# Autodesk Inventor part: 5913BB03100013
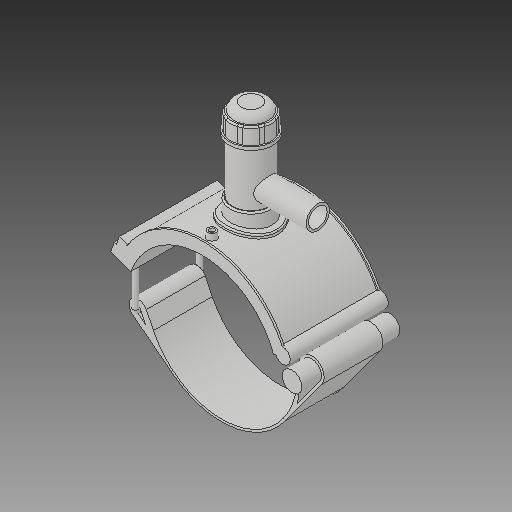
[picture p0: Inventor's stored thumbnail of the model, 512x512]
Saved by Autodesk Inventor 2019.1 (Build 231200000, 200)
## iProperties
Created: 2017-07
Part Number: 5913BB03100013
Material: Generic
Description: PLASSON HIGH VOLUME TAPPING TEE 10''IPS x 1 1/4''IPS
Document SubType Name: Modeling
Designer: KIM
Mass: 1712.7 g
Surface Area: 2671.49 cm^2
Volume: 1712.7 cm^3
Density: 1 g/cm^3
Appearance: Default
Author: KIM
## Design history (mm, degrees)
derived "5913B.ipt"
feature "Solid1::5913B.ipt"
feature "Solid2::5913B.ipt"
feature "Solid4::5913B.ipt"
feature "Solid5::5913B.ipt"
tag "TaggingFeature1"
body "Solid1"
body "Solid2"
other parameters: "d0" = 272.7, "d2" = 449.58, "d3" = 68.175, "d4" = 176.022, "d5" = 0, "d6" = 0.1, "d8" = 0, "d40" = 161.65656, "d41" = 95.445, "d43" = 0, "d45" = 0, "d47" = 261.0522, "d78" = 166.35, "d79" = 15, "d80" = 70.4088, "d82" = 5 deg, "d84" = 4, "d85" = 14, "d86" = 0, "d87" = 3, "d88" = 0, "d96" = 317.09556, "d97" = 3.52044, "d98" = 0, "d102" = 2.727, "d120" = 140 deg, "d121" = 24.228, "d122" = 20 deg, "d123" = 777.195, "d124" = 186.5268, "d126" = 0, "d153" = 176.022, "d154" = 0, "d159" = 7.6356, "d162" = 105.6132, "d163" = 0, "d164" = 136.35, "d169" = 4.0905, "d170" = 11.4534, "d172" = 0, "d173" = 1, "d175" = 136.35, "d176" = 20 deg, "d177" = 19.089, "d178" = 38.178, "d180" = 0, "d183" = 15.2712, "d184" = 15.2712, "d187" = 155.439, "d188" = 11.4534, "d189" = 19.089, "d190" = 0, "d191" = 233.1585, "d193" = 9.8172, "d194" = 4.9086, "d195" = 90 deg, "d197" = 0, "d199" = 0, "d200" = 19.089, "d202" = 0, "d203" = 194.818, "d204" = 74.35165, "d205" = 54.78543, "d206" = 66.52516, "d207" = 146.1135, "d208" = 151.95804, "d209" = 181.18074, "d210" = 67.30781, "d211" = 78.2649, "d212" = 62.61192, "d213" = 48.492, "d216" = 0, "d217" = 27.27, "d218" = 13.635, "d219" = 2.727, "d222" = 272.7, "d224" = 0, "d230" = 2.727, "d257" = 211.28, "d258" = 119.888, "d259" = 33.68, "d260" = 42.1, "d263" = 179.832, "d265" = 0, "d267" = 13.00006, "d268" = 2.60001, "d269" = 2.60001, "d271" = 2.60001, "d273" = 0, "d274" = 23.56194, "d275" = 218.16, "d277" = 109.08, "d278" = 436.32, "d280" = 0, "d281" = 272.7, "d283" = 0, "d285" = 0, "d290" = 27.27, "d291" = 35.451, "d293" = 149.985, "d294" = 140.4405, "d296" = 40.905, "d297" = 32.724, "d_" = 272.7, "B_" = 179.832, "L_" = 176.022, "d_t" = 6, "H_2" = 194.818, "H_1" = 74.93, "d_1" = 42.1, "H_" = 119.888, "d1" = 310.878, "d192" = 9.8172
